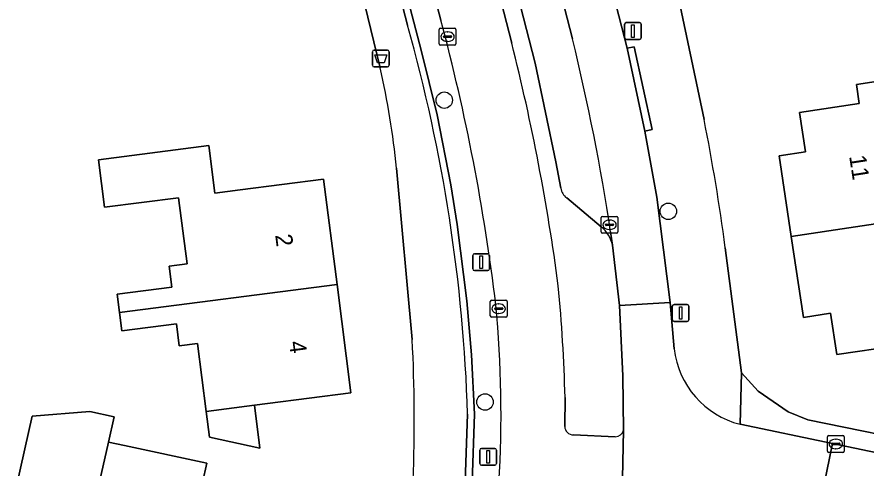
# Model space of a CAD drawing. Extents: x 161772 to 163126, y 383092 to 383917.
# Drawn here: x 161946.7 to 161997.2, y 383370 to 383396.8 of the extents above; entities that cross this region are included whole.
import ezdxf

# ---------------------------------------------------------------- set-up
doc = ezdxf.new("R2010")
doc.units = 0
for name, color, linetype in [('IMGEO_Afvalbak', 7, 'Continuous'), ('IMGEO_Berm_open', 7, 'Continuous'), ('IMGEO_Boom', 7, 'Continuous'), ('IMGEO_Erf', 7, 'Continuous'), ('IMGEO_Fietspad_gesloten', 7, 'Continuous'), ('IMGEO_Groenvoorziening', 7, 'Continuous'), ('IMGEO_Haag', 7, 'Continuous'), ('IMGEO_Kolk', 7, 'Continuous'), ('IMGEO_Lichtmast', 7, 'Continuous'), ('IMGEO_Pand', 7, 'Continuous'), ('IMGEO_Pand_nummerreeks', 7, 'Continuous'), ('IMGEO_Parkeervlak_open', 7, 'Continuous'), ('IMGEO_Rijbaan_lokaal_gesloten', 7, 'Continuous'), ('IMGEO_Rijbaan_lokaal_open', 7, 'Continuous'), ('IMGEO_Verkeersbordpaal', 7, 'Continuous'), ('IMGEO_Voetpad_gesloten', 7, 'Continuous'), ('IMGEO_Voetpad_open', 7, 'Continuous')]:
    doc.layers.add(name, color=color, linetype=linetype)

msp = doc.modelspace()

# ---------------------------------------------------------------- linework, layer by layer
at = {"layer": 'IMGEO_Afvalbak'}
for p, q in [((161967.853, 383393.939), (161967.853, 383394.739)), ((161967.853, 383394.739), (161967.853, 383393.939)), ((161967.953, 383394.839), (161968.743, 383394.839)), ((161968.743, 383394.839), (161967.953, 383394.839)), ((161968.843, 383394.739), (161968.843, 383393.939)), ((161968.843, 383393.939), (161968.843, 383394.739)), ((161968.743, 383393.839), (161967.953, 383393.839)), ((161967.953, 383393.839), (161968.743, 383393.839))]:
    msp.add_line(p, q, dxfattribs=at)
msp.add_lwpolyline([(161967.996, 383394.553), (161968.7, 383394.553), (161968.551, 383394.083), (161968.145, 383394.083), (161967.996, 383394.553)], dxfattribs=at)
for centre, start, end in [((161967.953, 383394.739), 90, 180), ((161967.953, 383394.739), 90, 180), ((161968.743, 383394.739), 0, 90), ((161968.743, 383394.739), 360, 90), ((161967.953, 383393.939), 180, 270), ((161967.953, 383393.939), 180, 270), ((161968.743, 383393.939), 270, 0), ((161968.743, 383393.939), 270, 0)]:
    msp.add_arc(centre, 0.1, start, end, dxfattribs=at)
at = {"layer": 'IMGEO_Berm_open'}
for points in [[(161960.66, 383455.182), (161976.137, 383395.25)], [(161979.059, 383386.635), (161978.765, 383388.191), (161977.523, 383394.063), (161974.044, 383407.626), (161973.608, 383407.52), (161972.355, 383412.364), (161972.788, 383412.467), (161964.622, 383444.131)], [(161981.46, 383384.34), (161979.41, 383386.052)], [(161982.784, 383372.242), (161982.74, 383375.487), (161982.536, 383379.669), (161982.127, 383383.237)], [(161979.305, 383374.2), (161979.293, 383372.478)], [(161979.807, 383371.969), (161982.294, 383371.857)]]:
    msp.add_lwpolyline(points, dxfattribs=at)
for centre, radius, start, end in [((161852.637, 383364.07), 127.375, 7.55991, 14.16929), ((161979.884, 383386.734), 0.831, 186.8688, 235.232), ((161980.119, 383382.776), 2.06, 12.9303, 49.3936), ((161886.103, 383371.901), 93.23, 1.41281, 5.49441), ((161979.795, 383372.471), 0.502, 179.2073, 271.3528), ((161982.261, 383372.404), 0.548, 273.498, 342.8165)]:
    msp.add_arc(centre, radius, start, end, dxfattribs=at)
at = {"layer": 'IMGEO_Boom'}
for centre in [(161972.124, 383391.861), (161985.446, 383385.256), (161974.547, 383373.924)]:
    msp.add_circle(centre, 0.489, dxfattribs=at)
at = {"layer": 'IMGEO_Erf'}
for points in [[(162013.474, 383465.049), (162000.265, 383462.051), (162000.295, 383461.907), (161996.785, 383460.931), (161992.404, 383459.714), (161973.318, 383454.411), (161972.09, 383452.564), (161979.364, 383425.078), (161979.14, 383425.031), (161985.923, 383398.52), (161987.571, 383390.708)], [(161988.831, 383383.094), (161989.798, 383375.666), (161990.795, 383374.566), (161992.579, 383373.341), (161993.75, 383372.87), (162001.33, 383371.327), (162032.857, 383365.301), (162067.97, 383400.221), (162013.474, 383465.049)], [(161968.312, 383393.79), (161964.267, 383410.402), (161955.259, 383445.271)], [(161970.218, 383377.639), (161969.284, 383387.816)], [(161946.718, 383369.015), (161947.624, 383373.087), (161951.056, 383373.363), (161952.489, 383373.044), (161952.156, 383371.547), (161953.109, 383371.343), (161957.998, 383370.297), (161957.751, 383369.143)]]:
    msp.add_lwpolyline(points, dxfattribs=at)
for points in [[(161996.802, 383391.666), (161996.633, 383392.787), (162000, 383393.298), (162003.388, 383393.812), (162003.598, 383392.422), (162005.687, 383392.739), (162006.995, 383391.883), (162007.878, 383386.026), (162007.97, 383385.417), (162009.203, 383385.604), (162010.81, 383374.95), (162006.334, 383374.271), (162005.861, 383377.41), (162000, 383376.543), (161999.136, 383376.413), (161999.006, 383377.272), (161995.462, 383376.738), (161995.092, 383379.195), (161993.48, 383378.952), (161992.757, 383383.75), (161992.033, 383388.552), (161993.599, 383388.788), (161993.246, 383391.13)], [(161952.811, 383379.239), (161952.672, 383380.326), (161955.927, 383380.742), (161955.765, 383382.006), (161956.828, 383382.142), (161956.325, 383386.059), (161951.931, 383385.495), (161951.568, 383388.322), (161958.117, 383389.163), (161958.479, 383386.334), (161959.992, 383386.528), (161964.951, 383387.163), (161965.752, 383380.9), (161966.575, 383374.467), (161961.616, 383373.833), (161960.839, 383373.734), (161961.165, 383371.186), (161958.158, 383371.829), (161957.961, 383373.365), (161957.443, 383377.406), (161956.367, 383377.268), (161956.201, 383378.568), (161952.951, 383378.152)]]:
    msp.add_lwpolyline(points, close=True, dxfattribs=at)
for centre, radius, start, end in [((161921.363, 383383.085), 48.154, 5.6381, 12.8445), ((161873.375, 383367.899), 116.451, 7.49749, 11.29534), ((161880.607, 383372.91), 89.736, 357.67817, 3.02055)]:
    msp.add_arc(centre, radius, start, end, dxfattribs=at)
at = {"layer": 'IMGEO_Fietspad_gesloten'}
for points in [[(161952.442, 383474.059), (161953.677, 383468.263), (161953.29, 383468.191), (161956.569, 383455.884), (161959.186, 383445.78), (161968.079, 383411.396), (161969.508, 383405.824), (161971.921, 383396.62)], [(161976.137, 383395.25), (161960.66, 383455.182)], [(161979.293, 383372.478), (161979.305, 383374.2)], [(161982.294, 383371.857), (161979.807, 383371.969)], [(161982.703, 383368.423), (161982.784, 383372.242)]]:
    msp.add_lwpolyline(points, dxfattribs=at)
for centre, radius, start, end in [((161853.206, 383364.887), 122.883, 6.92298, 14.96535), ((161852.637, 383364.07), 127.375, 7.55991, 14.16929), ((161886.103, 383371.901), 93.23, 1.41281, 5.49441), ((161907.089, 383373.249), 68.409, 356.52541, 5.41022), ((161979.795, 383372.471), 0.502, 179.2073, 271.3528), ((161982.261, 383372.404), 0.548, 273.498, 342.8165)]:
    msp.add_arc(centre, radius, start, end, dxfattribs=at)
at = {"layer": 'IMGEO_Groenvoorziening'}
for points in [[(161971.921, 383396.62), (161969.508, 383405.824), (161967.979, 383405.437), (161970.76, 383394.838), (161971.696, 383390.984), (161972.516, 383386.826), (161972.897, 383384.465), (161973.463, 383379.935), (161973.746, 383376.726), (161973.914, 383373.196), (161973.773, 383369.167), (161975.372, 383369.103)], [(161973.513, 383373.196), (161973.373, 383369.183), (161973.773, 383369.167), (161973.914, 383373.196), (161973.746, 383376.726), (161973.463, 383379.935), (161972.897, 383384.465), (161972.516, 383386.826), (161971.696, 383390.984), (161970.76, 383394.838), (161967.979, 383405.437), (161967.591, 383405.339), (161969.94, 383396.311)]]:
    msp.add_lwpolyline(points, dxfattribs=at)
for centre, radius, start, end in [((161853.206, 383364.887), 122.883, 6.92298, 14.96535), ((161877.137, 383370.132), 96.425, 1.82077, 15.75313), ((161907.089, 383373.249), 68.409, 356.52541, 5.41022)]:
    msp.add_arc(centre, radius, start, end, dxfattribs=at)
at = {"layer": 'IMGEO_Haag'}
msp.add_lwpolyline([(161973.513, 383373.196), (161973.373, 383369.183), (161973.773, 383369.167), (161973.914, 383373.196), (161973.746, 383376.726), (161973.463, 383379.935), (161972.897, 383384.465), (161972.516, 383386.826), (161971.696, 383390.984), (161970.76, 383394.838), (161967.979, 383405.437), (161967.591, 383405.339), (161969.94, 383396.311)], dxfattribs=at)
msp.add_arc((161877.137, 383370.132), 96.425, 1.82077, 15.75313, dxfattribs=at)
at = {"layer": 'IMGEO_Kolk'}
for p, q in [((161971.893, 383396.134), (161972.745, 383396.134)), ((161971.818, 383395.208), (161971.818, 383396.06)), ((161972.077, 383395.628), (161972.077, 383395.64)), ((161972.12, 383395.677), (161972.518, 383395.677)), ((161972.306, 383395.914), (161972.331, 383395.914)), ((161972.561, 383395.64), (161972.561, 383395.628)), ((161972.819, 383396.06), (161972.819, 383395.208)), ((161972.745, 383395.134), (161971.893, 383395.134)), ((161972.515, 383395.591), (161972.117, 383395.591)), ((161972.329, 383395.354), (161972.304, 383395.354)), ((161981.45, 383384.031), (161981.45, 383384.883)), ((161981.525, 383384.957), (161982.377, 383384.957)), ((161981.752, 383384.5), (161982.15, 383384.5)), ((161981.938, 383384.737), (161981.963, 383384.737)), ((161982.451, 383384.883), (161982.451, 383384.031)), ((161981.709, 383384.451), (161981.709, 383384.463)), ((161982.147, 383384.414), (161981.749, 383384.414)), ((161981.961, 383384.177), (161981.936, 383384.177)), ((161982.193, 383384.463), (161982.193, 383384.451)), ((161982.377, 383383.957), (161981.525, 383383.957)), ((161974.937, 383379.969), (161975.789, 383379.969)), ((161974.862, 383379.043), (161974.862, 383379.895)), ((161975.121, 383379.463), (161975.121, 383379.475)), ((161975.164, 383379.512), (161975.562, 383379.512)), ((161975.35, 383379.749), (161975.375, 383379.749)), ((161975.605, 383379.475), (161975.605, 383379.463)), ((161975.863, 383379.895), (161975.863, 383379.043)), ((161975.789, 383378.969), (161974.937, 383378.969)), ((161975.559, 383379.426), (161975.161, 383379.426)), ((161975.373, 383379.189), (161975.348, 383379.189)), ((161994.98, 383371.931), (161995.832, 383371.931)), ((161994.905, 383371.005), (161994.905, 383371.857)), ((161995.164, 383371.425), (161995.164, 383371.437)), ((161995.602, 383371.388), (161995.204, 383371.388)), ((161995.207, 383371.474), (161995.605, 383371.474)), ((161995.393, 383371.711), (161995.418, 383371.711)), ((161995.648, 383371.437), (161995.648, 383371.425)), ((161995.906, 383371.857), (161995.906, 383371.005)), ((161995.832, 383370.931), (161994.98, 383370.931)), ((161995.416, 383371.151), (161995.391, 383371.151))]:
    msp.add_line(p, q, dxfattribs=at)
for points in [[(161971.893, 383396.134), (161972.745, 383396.134)], [(161971.818, 383395.208), (161971.818, 383396.06)], [(161972.819, 383396.06), (161972.819, 383395.208)], [(161972.745, 383395.134), (161971.893, 383395.134)], [(161981.45, 383384.031), (161981.45, 383384.883)], [(161981.525, 383384.957), (161982.377, 383384.957)], [(161982.451, 383384.883), (161982.451, 383384.031)], [(161982.377, 383383.957), (161981.525, 383383.957)], [(161974.937, 383379.969), (161975.789, 383379.969)], [(161974.862, 383379.043), (161974.862, 383379.895)], [(161975.863, 383379.895), (161975.863, 383379.043)], [(161975.789, 383378.969), (161974.937, 383378.969)], [(161994.98, 383371.931), (161995.832, 383371.931)], [(161994.905, 383371.005), (161994.905, 383371.857)], [(161995.906, 383371.857), (161995.906, 383371.005)], [(161995.832, 383370.931), (161994.98, 383370.931)]]:
    msp.add_lwpolyline(points, dxfattribs=at)
for centre, radius, start, end in [((161971.895, 383396.058), 0.0765, 91.552, 178.448), ((161971.895, 383396.058), 0.0765, 91.552, 178.448), ((161972.743, 383396.058), 0.0765, 1.552, 88.448), ((161972.743, 383396.058), 0.0765, 1.552, 88.448), ((161972.117, 383395.637), 0.0403, 85.8775, 175.7526), ((161972.114, 383395.627), 0.0366, 178.938, 274.7102), ((161972.518, 383395.634), 0.043, 264.8664, 352.4533), ((161972.522, 383395.639), 0.0386, 1.7309, 96.639), ((161971.895, 383395.21), 0.0765, 181.552, 268.448), ((161971.895, 383395.21), 0.0765, 181.552, 268.448), ((161972.743, 383395.21), 0.0765, 271.552, 358.448), ((161972.743, 383395.21), 0.0765, 271.552, 358.448), ((161981.527, 383384.881), 0.0765, 91.552, 178.448), ((161981.527, 383384.881), 0.0765, 91.552, 178.448), ((161981.749, 383384.46), 0.0403, 85.8775, 175.7526), ((161982.154, 383384.462), 0.0386, 1.7309, 96.639), ((161982.375, 383384.881), 0.0765, 1.552, 88.448), ((161982.375, 383384.881), 0.0765, 1.552, 88.448), ((161981.527, 383384.033), 0.0765, 181.552, 268.448), ((161981.527, 383384.033), 0.0765, 181.552, 268.448), ((161981.746, 383384.45), 0.0366, 178.938, 274.7102), ((161982.15, 383384.457), 0.043, 264.8664, 352.4533), ((161982.375, 383384.033), 0.0765, 271.552, 358.448), ((161982.375, 383384.033), 0.0765, 271.552, 358.448), ((161974.939, 383379.893), 0.0765, 91.552, 178.448), ((161974.939, 383379.893), 0.0765, 91.552, 178.448), ((161975.787, 383379.893), 0.0765, 1.552, 88.448), ((161975.787, 383379.893), 0.0765, 1.552, 88.448), ((161975.161, 383379.472), 0.0403, 85.8775, 175.7526), ((161975.158, 383379.462), 0.0366, 178.938, 274.7102), ((161975.562, 383379.469), 0.043, 264.8664, 352.4533), ((161975.566, 383379.474), 0.0386, 1.7309, 96.639), ((161974.939, 383379.045), 0.0765, 181.552, 268.448), ((161974.939, 383379.045), 0.0765, 181.552, 268.448), ((161975.787, 383379.045), 0.0765, 271.552, 358.448), ((161975.787, 383379.045), 0.0765, 271.552, 358.448), ((161994.982, 383371.855), 0.0765, 91.552, 178.448), ((161994.982, 383371.855), 0.0765, 91.552, 178.448), ((161995.83, 383371.855), 0.0765, 1.552, 88.448), ((161995.83, 383371.855), 0.0765, 1.552, 88.448), ((161995.204, 383371.434), 0.0403, 85.8775, 175.7526), ((161995.201, 383371.424), 0.0366, 178.938, 274.7102), ((161995.605, 383371.431), 0.043, 264.8664, 352.4533), ((161995.609, 383371.436), 0.0386, 1.7309, 96.639), ((161994.982, 383371.007), 0.0765, 181.552, 268.448), ((161994.982, 383371.007), 0.0765, 181.552, 268.448), ((161995.83, 383371.007), 0.0765, 271.552, 358.448), ((161995.83, 383371.007), 0.0765, 271.552, 358.448)]:
    msp.add_arc(centre, radius, start, end, dxfattribs=at)
for centre, major_axis, ratio, start_param, end_param in [((161972.305, 383395.634), (-0.387, 0.002), 0.722429, 4.712389, 7.853982), ((161972.33, 383395.634), (-0.39, 0.002), 0.717154, 1.570796, 4.712389), ((161981.937, 383384.457), (-0.387, 0.002), 0.722429, 4.712389, 7.853982), ((161981.962, 383384.457), (-0.39, 0.002), 0.717154, 1.570796, 4.712389), ((161975.349, 383379.469), (-0.387, 0.002), 0.722429, 4.712389, 7.853982), ((161975.374, 383379.469), (-0.39, 0.002), 0.717154, 1.570796, 4.712389), ((161995.392, 383371.431), (-0.387, 0.002), 0.722429, 4.712389, 7.853982), ((161995.417, 383371.431), (-0.39, 0.002), 0.717154, 1.570796, 4.712389)]:
    msp.add_ellipse(centre, major_axis=major_axis, ratio=ratio, start_param=start_param, end_param=end_param, dxfattribs=at)
at = {"layer": 'IMGEO_Lichtmast'}
for p, q in [((161982.846, 383395.568), (161982.846, 383396.368)), ((161982.846, 383396.368), (161982.846, 383395.568)), ((161982.946, 383396.468), (161983.736, 383396.468)), ((161983.736, 383396.468), (161982.946, 383396.468)), ((161983.836, 383396.368), (161983.836, 383395.568)), ((161983.836, 383395.568), (161983.836, 383396.368)), ((161983.736, 383395.468), (161982.946, 383395.468)), ((161982.946, 383395.468), (161983.736, 383395.468)), ((161973.819, 383381.835), (161973.819, 383382.635)), ((161973.819, 383382.635), (161973.819, 383381.835)), ((161973.919, 383382.735), (161974.709, 383382.735)), ((161974.709, 383382.735), (161973.919, 383382.735)), ((161974.809, 383382.635), (161974.809, 383381.835)), ((161974.809, 383381.835), (161974.809, 383382.635)), ((161974.709, 383381.735), (161973.919, 383381.735)), ((161973.919, 383381.735), (161974.709, 383381.735)), ((161985.684, 383378.814), (161985.684, 383379.614)), ((161985.684, 383379.614), (161985.684, 383378.814)), ((161985.784, 383379.714), (161986.574, 383379.714)), ((161986.574, 383379.714), (161985.784, 383379.714)), ((161986.674, 383379.614), (161986.674, 383378.814)), ((161986.674, 383378.814), (161986.674, 383379.614)), ((161986.574, 383378.714), (161985.784, 383378.714)), ((161985.784, 383378.714), (161986.574, 383378.714))]:
    msp.add_line(p, q, dxfattribs=at)
for points in [[(161983.266, 383396.343), (161983.416, 383396.343), (161983.416, 383395.593), (161983.266, 383395.593), (161983.266, 383396.343)], [(161974.239, 383382.61), (161974.389, 383382.61), (161974.389, 383381.86), (161974.239, 383381.86), (161974.239, 383382.61)], [(161986.104, 383379.589), (161986.254, 383379.589), (161986.254, 383378.839), (161986.104, 383378.839), (161986.104, 383379.589)]]:
    msp.add_lwpolyline(points, dxfattribs=at)
for centre, start, end in [((161982.946, 383396.368), 90, 180), ((161982.946, 383396.368), 90, 180), ((161983.736, 383396.368), 0, 90), ((161983.736, 383396.368), 360, 90), ((161982.946, 383395.568), 180, 270), ((161982.946, 383395.568), 180, 270), ((161983.736, 383395.568), 270, 0), ((161983.736, 383395.568), 270, 0), ((161973.919, 383382.635), 90, 180), ((161973.919, 383382.635), 90, 180), ((161974.709, 383382.635), 0, 90), ((161974.709, 383382.635), 360, 90), ((161973.919, 383381.835), 180, 270), ((161973.919, 383381.835), 180, 270), ((161974.709, 383381.835), 270, 0), ((161974.709, 383381.835), 270, 0), ((161985.784, 383379.614), 90, 180), ((161985.784, 383379.614), 90, 180), ((161986.574, 383379.614), 0, 90), ((161986.574, 383379.614), 360, 90), ((161985.784, 383378.814), 180, 270), ((161985.784, 383378.814), 180, 270), ((161986.574, 383378.814), 270, 0), ((161986.574, 383378.814), 270, 0)]:
    msp.add_arc(centre, 0.1, start, end, dxfattribs=at)
at = {"layer": 'IMGEO_Pand'}
for points in [[(162007.878, 383386.026), (162006.995, 383391.883), (162005.687, 383392.739), (162003.598, 383392.422), (162003.388, 383393.812), (162000, 383393.298), (161996.633, 383392.787), (161996.802, 383391.666), (161993.246, 383391.13), (161993.599, 383388.788), (161992.033, 383388.552), (161992.757, 383383.75), (162000, 383384.84)], [(161964.951, 383387.163), (161959.992, 383386.528), (161958.479, 383386.334), (161958.117, 383389.163), (161951.568, 383388.322), (161951.931, 383385.495), (161956.325, 383386.059), (161956.828, 383382.142), (161955.765, 383382.006), (161955.927, 383380.742), (161952.672, 383380.326), (161952.811, 383379.239), (161965.752, 383380.9)], [(162007.878, 383386.026), (162000, 383384.84), (161992.757, 383383.75), (161993.48, 383378.952), (161995.092, 383379.195), (161995.462, 383376.738), (161999.006, 383377.272), (161999.136, 383376.413), (162000, 383376.543), (162005.861, 383377.41), (162006.334, 383374.271), (162010.81, 383374.95), (162009.203, 383385.604), (162007.97, 383385.417)], [(161965.752, 383380.9), (161952.811, 383379.239), (161952.951, 383378.152), (161956.201, 383378.568), (161956.367, 383377.268), (161957.443, 383377.406), (161957.961, 383373.365), (161960.839, 383373.734), (161961.616, 383373.833), (161966.575, 383374.467)], [(161960.839, 383373.734), (161957.961, 383373.365), (161958.158, 383371.829), (161961.165, 383371.186)], [(161952.156, 383371.547), (161952.489, 383373.044), (161951.056, 383373.363), (161947.624, 383373.087), (161946.718, 383369.015), (161949.997, 383368.286), (161950.263, 383369.483), (161951.629, 383369.179)], [(161966.208, 383367.333), (161966.242, 383367.486), (161957.751, 383369.143), (161957.998, 383370.297), (161953.109, 383371.343), (161952.156, 383371.547), (161951.629, 383369.179), (161951.32, 383367.789), (161949.903, 383361.425), (161949.084, 383357.595), (161949.25, 383357.56), (161955.008, 383356.328), (161960.733, 383354.757), (161961.226, 383356.243), (161963.646, 383355.724), (161963.689, 383355.927)]]:
    msp.add_lwpolyline(points, close=True, dxfattribs=at)
at = {"layer": 'IMGEO_Parkeervlak_open'}
for points in [[(161979.748, 383395.513), (161966.176, 383448.104)], [(161974.044, 383407.626), (161977.523, 383394.063)], [(161977.523, 383394.063), (161978.765, 383388.191)], [(161978.765, 383388.191), (161979.059, 383386.635)], [(161979.41, 383386.052), (161981.46, 383384.34)], [(161982.127, 383383.237), (161982.017, 383384.028)]]:
    msp.add_lwpolyline(points, dxfattribs=at)
for centre, radius, start, end in [((161851.687, 383364.246), 131.822, 8.63053, 13.72058), ((161979.884, 383386.734), 0.831, 186.8688, 235.232), ((161980.119, 383382.776), 2.06, 12.9303, 49.3936)]:
    msp.add_arc(centre, radius, start, end, dxfattribs=at)
at = {"layer": 'IMGEO_Rijbaan_lokaal_gesloten'}
msp.add_lwpolyline([(161982.017, 383384.028), (161982.127, 383383.237), (161982.536, 383379.669), (161985.559, 383379.831), (161984.753, 383386.092), (161984.052, 383390.021), (161982.996, 383394.943), (161979.878, 383407.029), (161978.62, 383411.896), (161976.872, 383418.678), (161974.349, 383428.407), (161969.081, 383448.833), (161966.176, 383448.104), (161979.748, 383395.513)], dxfattribs=at)
msp.add_arc((161851.687, 383364.246), 131.822, 8.63053, 13.72058, dxfattribs=at)
at = {"layer": 'IMGEO_Rijbaan_lokaal_open'}
for points in [[(161985.786, 383377.081), (161985.559, 383379.831), (161982.536, 383379.669), (161982.74, 383375.487), (161982.784, 383372.242), (161982.703, 383368.423)], [(161995.201, 383371.459), (161989.716, 383372.599)], [(161992.197, 383368.496), (161993.454, 383368.299), (161993.858, 383368.213), (161994.524, 383368.077), (161995.201, 383371.459)], [(162031.731, 383363.861), (162026.624, 383364.907), (162022.901, 383365.67), (161995.201, 383371.459), (161994.524, 383368.077), (162031.651, 383360.514), (162032.009, 383360.453)]]:
    msp.add_lwpolyline(points, dxfattribs=at)
msp.add_arc((161991.04, 383377.724), 5.293, 186.9763, 255.5149, dxfattribs=at)
at = {"layer": 'IMGEO_Verkeersbordpaal'}
for p, q in [((161974.237, 383370.264), (161974.237, 383371.064)), ((161974.237, 383371.064), (161974.237, 383370.264)), ((161974.337, 383371.164), (161975.127, 383371.164)), ((161975.127, 383371.164), (161974.337, 383371.164)), ((161975.227, 383371.064), (161975.227, 383370.264)), ((161975.227, 383370.264), (161975.227, 383371.064)), ((161975.127, 383370.164), (161974.337, 383370.164)), ((161974.337, 383370.164), (161975.127, 383370.164))]:
    msp.add_line(p, q, dxfattribs=at)
msp.add_lwpolyline([(161974.657, 383371.039), (161974.807, 383371.039), (161974.807, 383370.289), (161974.657, 383370.289), (161974.657, 383371.039)], dxfattribs=at)
for centre, start, end in [((161974.337, 383371.064), 90, 180), ((161974.337, 383371.064), 90, 180), ((161975.127, 383371.064), 0, 90), ((161975.127, 383371.064), 360, 90), ((161974.337, 383370.264), 180, 270), ((161974.337, 383370.264), 180, 270), ((161975.127, 383370.264), 270, 0), ((161975.127, 383370.264), 270, 0)]:
    msp.add_arc(centre, 0.1, start, end, dxfattribs=at)
at = {"layer": 'IMGEO_Voetpad_gesloten'}
for points in [[(161969.94, 383396.311), (161967.591, 383405.339), (161967.979, 383405.437), (161969.508, 383405.824), (161968.079, 383411.396), (161966.55, 383410.99), (161966.164, 383410.887), (161957.28, 383445.3), (161957.668, 383445.398), (161959.186, 383445.78), (161956.569, 383455.884), (161955.312, 383455.554), (161954.925, 383455.453), (161952.31, 383465.637)], [(161950.628, 383462.756), (161952.504, 383454.913), (161952.601, 383454.538), (161954.993, 383445.237), (161955.259, 383445.271), (161964.267, 383410.402), (161968.312, 383393.79)], [(162069.608, 383398.523), (162067.97, 383400.221), (162032.857, 383365.301), (162001.33, 383371.327), (161993.75, 383372.87), (161992.579, 383373.341), (161990.795, 383374.566), (161989.798, 383375.666), (161989.716, 383372.599), (161995.201, 383371.459), (162022.901, 383365.67), (162023.012, 383366.206), (162026.732, 383365.428), (162026.624, 383364.907), (162031.731, 383363.861)], [(161969.284, 383387.816), (161970.218, 383377.639)], [(161970.269, 383369.275), (161970.168, 383368.269), (161973.308, 383367.97), (161973.707, 383367.951), (161975.312, 383367.874), (161975.372, 383369.103), (161973.773, 383369.167), (161973.373, 383369.183), (161973.513, 383373.196)]]:
    msp.add_lwpolyline(points, dxfattribs=at)
for centre, radius, start, end in [((161877.137, 383370.132), 96.425, 1.82077, 15.75313), ((161921.363, 383383.085), 48.154, 5.6381, 12.8445), ((161880.607, 383372.91), 89.736, 357.67817, 3.02055)]:
    msp.add_arc(centre, radius, start, end, dxfattribs=at)
at = {"layer": 'IMGEO_Voetpad_open'}
for points in [[(161968.765, 383450.11), (161969.081, 383448.833), (161974.349, 383428.407), (161974.791, 383428.524), (161977.289, 383418.811), (161976.872, 383418.678), (161978.62, 383411.896), (161979.059, 383412.019), (161980.294, 383407.171), (161979.878, 383407.029), (161982.996, 383394.943), (161983.422, 383395.021), (161984.476, 383390.121), (161984.052, 383390.021), (161984.753, 383386.092), (161985.559, 383379.831), (161985.786, 383377.081)], [(161987.571, 383390.708), (161985.923, 383398.52), (161979.14, 383425.031)], [(161989.716, 383372.599), (161989.798, 383375.666), (161988.831, 383383.094)]]:
    msp.add_lwpolyline(points, dxfattribs=at)
msp.add_lwpolyline([(161984.052, 383390.021), (161984.476, 383390.121), (161983.422, 383395.021), (161982.996, 383394.943)], close=True, dxfattribs=at)
for centre, radius, start, end in [((161873.375, 383367.899), 116.451, 7.49749, 11.29534), ((161991.04, 383377.724), 5.293, 186.9763, 255.5149)]:
    msp.add_arc(centre, radius, start, end, dxfattribs=at)

# ---------------------------------------------------------------- texts
at = {"layer": 'IMGEO_Pand_nummerreeks'}
for s, rotation, p in [('11', 278.7533, (161996.196, 383388.53)), ('2', 277.2878, (161962.068, 383383.848)), ('4', 277.2878, (161962.881, 383377.498))]:
    msp.add_text(s, height=1, rotation=rotation, dxfattribs=at).set_placement(p)

doc.saveas('drawing.dxf')
